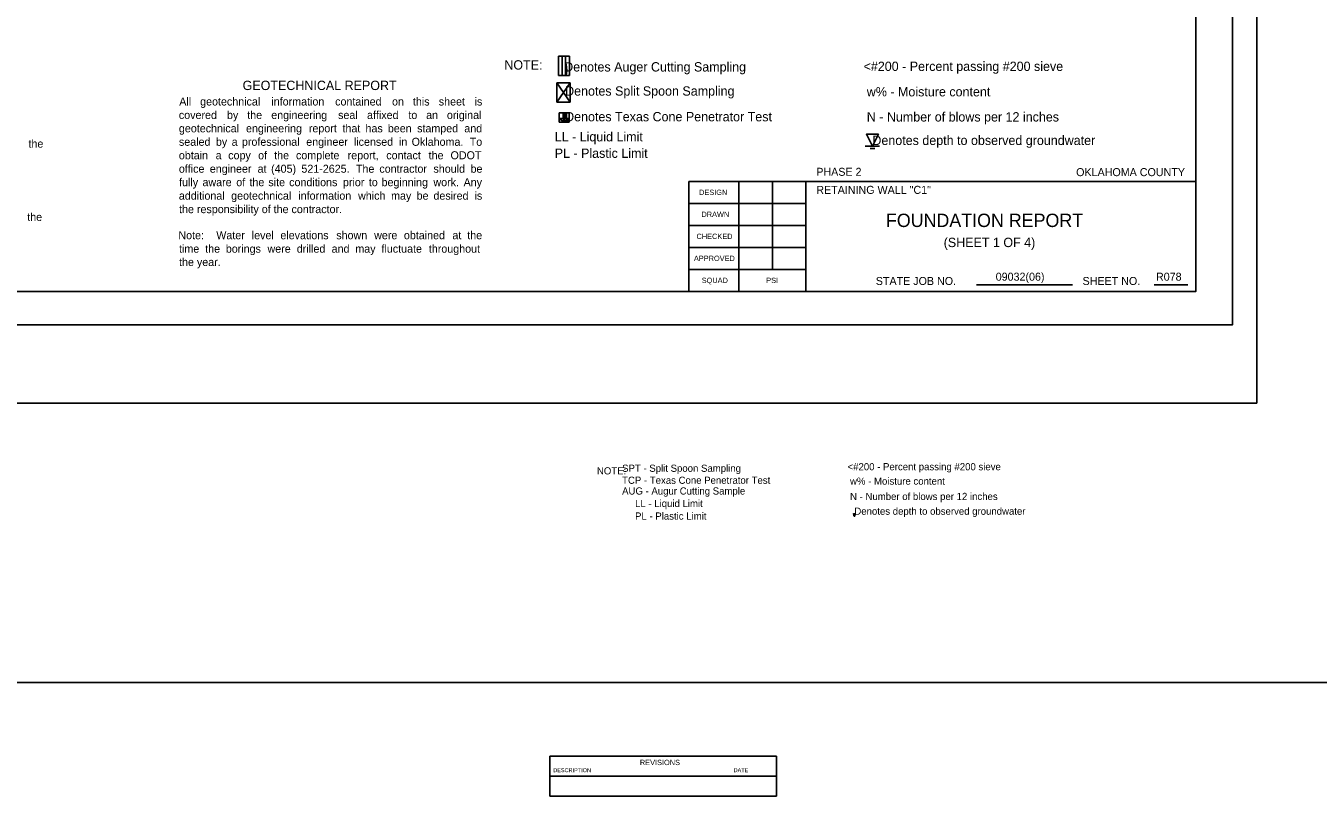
# Model space of a CAD drawing. Extents: x -6 to 173, y 24 to 64.
# Drawn here: x 24.17 to 43.55, y 24.08 to 35.63 of the extents above; entities that cross this region are included whole.
import ezdxf

# ---------------------------------------------------------------- set-up
doc = ezdxf.new("R2010")
doc.units = 0
for name, color, linetype in [('4', 7, 'Continuous'), ('REVBLK', 7, 'Continuous'), ('S', 7, 'Continuous'), ('SHT_Plot_Shape_Full', 7, 'Continuous'), ('SHT_Plot_Shape_Half', 7, 'Continuous'), ('SHT_Sheet_Border', 7, 'Continuous'), ('SHT_Standard_Sheet_Lines', 7, 'Continuous'), ('SHT_Standard_Sheet_Txt', 7, 'Continuous'), ('T', 7, 'Continuous'), ('T-5', 7, 'Continuous'), ('Text', 7, 'Continuous')]:
    doc.layers.add(name, color=color, linetype=linetype)

# ---------------------------------------------------------------- blocks, each defined once
blk = doc.blocks.new('DGRFC_WTLEV1')
for points in [[(-0.013, 0), (0.013, 0)], [(0, 0), (0.011, 0.021), (-0.011, 0.021), (0, 0)], [(-0.004, -0.004), (0.004, -0.004)]]:
    blk.add_lwpolyline(points)
blk = doc.blocks.new('DGRFC_WTLEV1_1')
for points in [[(-0.005, 0), (0.005, 0)], [(0, 0), (0.00417, 0.00833), (-0.00417, 0.00833), (0, 0)], [(-0.00167, -0.00167), (0.00167, -0.00167)]]:
    blk.add_lwpolyline(points)

msp = doc.modelspace()

# ---------------------------------------------------------------- linework, layer by layer
msp.add_line((32.155, 35.172), (32.155, 34.881))
for points in [[(32.155, 35.172), (32.322, 35.172)], [(32.322, 34.881), (32.322, 35.172)], [(32.155, 34.881), (32.322, 34.881)], [(32.155, 34.881), (32.322, 34.881)]]:
    msp.add_lwpolyline(points)
for points in [[(32.213, 35.172), (32.213, 34.881), (32.263, 34.881), (32.263, 35.172)], [(32.278, 35.005), (32.272, 35.047), (32.263, 35.087), (32.278, 35.005)], [(32.263, 35.087), (32.263, 34.881), (32.278, 35.005), (32.263, 35.087)], [(32.263, 34.881), (32.278, 34.922), (32.278, 35.005), (32.263, 34.881)], [(32.263, 34.881), (32.272, 34.881), (32.278, 34.922), (32.263, 34.881)], [(32.278, 34.922), (32.28, 34.963), (32.278, 35.005), (32.278, 34.922)]]:
    msp.add_lwpolyline(points, close=True)
at = {"layer": 'REVBLK'}
for p, q in [((32.025, 24.676), (35.425, 24.676)), ((32.025, 24.676), (32.025, 24.076)), ((35.425, 24.676), (35.425, 24.076)), ((32.025, 24.376), (35.425, 24.376)), ((32.025, 24.076), (35.425, 24.076))]:
    msp.add_line(p, q, dxfattribs=at)
at = {"layer": 'S'}
msp.add_lwpolyline([(-6.024, 64.421), (172.576, 64.421), (172.576, 25.783), (-6.024, 25.783)], close=True, dxfattribs=at)
at = {"layer": 'SHT_Plot_Shape_Full'}
msp.add_lwpolyline([(6.624, 53.971), (42.624, 53.971), (42.624, 29.971), (6.624, 29.971)], close=True, dxfattribs=at)
at = {"layer": 'SHT_Plot_Shape_Half'}
msp.add_lwpolyline([(8.262, 53.146), (42.262, 53.146), (42.262, 31.146), (8.262, 31.146)], close=True, dxfattribs=at)
at = {"layer": 'SHT_Sheet_Border'}
for p, q in [((34.112, 31.646), (34.112, 33.296)), ((34.112, 33.296), (41.712, 33.296)), ((35.862, 31.646), (35.862, 33.297))]:
    msp.add_line(p, q, dxfattribs=at)
msp.add_lwpolyline([(10.212, 52.646), (41.712, 52.646), (41.712, 31.646), (10.212, 31.646)], close=True, dxfattribs=at)
at = {"layer": 'SHT_Standard_Sheet_Lines'}
for p, q in [((34.862, 31.646), (34.862, 33.297)), ((35.362, 31.976), (35.362, 33.297)), ((38.422, 31.742), (39.863, 31.742)), ((41.087, 31.742), (41.59, 31.742))]:
    msp.add_line(p, q, dxfattribs=at)
for points in [[(35.862, 32.966), (34.112, 32.966)], [(35.862, 32.636), (34.112, 32.636)], [(35.862, 32.306), (34.112, 32.306)], [(35.862, 31.976), (34.112, 31.976)]]:
    msp.add_lwpolyline(points, dxfattribs=at)
at = {"layer": 'Text'}
for p, q in [((32.131, 34.481), (32.131, 34.773)), ((32.167, 34.181), (32.167, 34.322))]:
    msp.add_line(p, q, dxfattribs=at)
for points in [[(32.131, 34.481), (32.331, 34.773)], [(32.131, 34.773), (32.331, 34.481)], [(32.131, 34.773), (32.331, 34.773)], [(32.331, 34.481), (32.331, 34.773)], [(32.131, 34.481), (32.331, 34.481)], [(32.167, 34.322), (32.317, 34.322)], [(32.317, 34.181), (32.317, 34.322)], [(32.167, 34.181), (32.317, 34.181)]]:
    msp.add_lwpolyline(points, dxfattribs=at)
for points in [[(32.227, 34.237), (32.257, 34.322), (32.227, 34.322), (32.227, 34.237)], [(32.227, 34.237), (32.257, 34.237), (32.257, 34.322), (32.227, 34.237)], [(32.227, 34.237), (32.167, 34.237), (32.242, 34.181), (32.227, 34.237)], [(32.227, 34.237), (32.242, 34.181), (32.257, 34.237), (32.227, 34.237)], [(32.242, 34.181), (32.317, 34.237), (32.257, 34.237), (32.242, 34.181)]]:
    msp.add_lwpolyline(points, close=True, dxfattribs=at)

# ---------------------------------------------------------------- block references
at = {"xscale": 1.3824000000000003, "yscale": 1.3824000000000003}
msp.add_blockref('DGRFC_WTLEV1', (36.592, 28.283), dxfattribs=at)
at = {"layer": 'Text', "xscale": 21.6, "yscale": 21.6}
msp.add_blockref('DGRFC_WTLEV1_1', (36.863, 33.823), dxfattribs=at)

# ---------------------------------------------------------------- texts
at = {"layer": '4'}
msp.add_text('FOUNDATION REPORT', height=0.2, dxfattribs=at).set_placement((37.065, 32.611))
at = {"layer": 'REVBLK'}
for s, height, p in [('REVISIONS', 0.08, (33.376, 24.542)), ('DESCRIPTION', 0.06, (32.077, 24.436)), ('DATE', 0.06, (34.781, 24.436))]:
    msp.add_text(s, height=height, dxfattribs=at).set_placement(p)
at = {"layer": 'SHT_Standard_Sheet_Txt'}
for s, height, p in [('DESIGN', 0.08, (34.264, 33.091)), ('DRAWN', 0.08, (34.299, 32.761)), ('CHECKED', 0.08, (34.225, 32.431)), ('APPROVED', 0.08, (34.186, 32.101)), ('SQUAD', 0.08, (34.303, 31.771)), ('PSI', 0.08, (35.27, 31.771)), ('STATE JOB NO.', 0.12, (36.913, 31.742)), ('SHEET NO. ', 0.12, (40.013, 31.742))]:
    msp.add_text(s, height=height, dxfattribs=at).set_placement(p)
at = {"layer": 'T'}
for s, p in [('PHASE 2', (36.021, 33.379)), ('OKLAHOMA COUNTY', (39.917, 33.374)), ('RETAINING WALL "C1" ', (36.021, 33.108)), ('09032(06)', (38.711, 31.806)), ('R078', (41.114, 31.806))]:
    msp.add_text(s, height=0.12, dxfattribs=at).set_placement(p)
at = {"layer": 'T-5'}
msp.add_text('(SHEET 1 OF 4)', height=0.14, dxfattribs=at).set_placement((37.931, 32.31))
at = {"layer": 'Text'}
for s, height, p in [('NOTE:', 0.14, (31.344, 34.972)), ('    Denotes Auger Cutting Sampling', 0.14, (32.033, 34.943)), (' <#200 - Percent passing #200 sieve', 0.14, (36.678, 34.951)), ('GEOTECHNICAL REPORT', 0.14, (27.42, 34.665)), ('    Denotes Split Spoon Sampling', 0.14, (32.047, 34.581)), ('w% - Moisture content', 0.14, (36.778, 34.57)), ('All', 0.12, (26.47, 34.433)), ('geotechnical', 0.12, (26.783, 34.433)), ('information', 0.12, (27.851, 34.433)), ('contained', 0.12, (28.807, 34.433)), ('on', 0.12, (29.66, 34.433)), ('this', 0.12, (29.973, 34.433)), ('sheet', 0.12, (30.361, 34.433)), ('is ', 0.12, (30.897, 34.433)), ('covered', 0.12, (26.464, 34.231)), ('by', 0.12, (27.186, 34.231)), ('the', 0.12, (27.489, 34.231)), ('engineering', 0.12, (27.849, 34.231)), ('seal', 0.12, (28.851, 34.231)), ('affixed', 0.12, (29.285, 34.231)), ('to', 0.12, (29.905, 34.231)), ('an', 0.12, (30.171, 34.231)), ('original ', 0.12, (30.483, 34.231)), ('    Denotes Texas Cone Penetrator Test', 0.14, (32.047, 34.196)), ('N - Number of blows per 12 inches', 0.14, (36.778, 34.193)), ('geotechnical', 0.12, (26.465, 34.031)), ('engineering', 0.12, (27.471, 34.031)), ('report', 0.12, (28.413, 34.031)), ('that', 0.12, (28.917, 34.031)), ('has', 0.12, (29.262, 34.031)), ('been', 0.12, (29.597, 34.031)), ('stamped', 0.12, (30.036, 34.031)), ('and ', 0.12, (30.744, 34.031)), ('the ', 0.12, (24.209, 33.801)), ('sealed', 0.12, (26.465, 33.829)), ('by', 0.12, (27.019, 33.829)), ('a', 0.12, (27.256, 33.829)), ('professional', 0.12, (27.409, 33.829)), ('engineer', 0.12, (28.374, 33.829)), ('licensed', 0.12, (29.088, 33.829)), ('in', 0.12, (29.764, 33.829)), ('Oklahoma.', 0.12, (29.954, 33.829)), ('To ', 0.12, (30.825, 33.829)), (' LL - Liquid Limit', 0.14, (32.047, 33.895)), ('    Denotes depth to observed groundwater', 0.14, (36.654, 33.841)), ('obtain', 0.12, (26.464, 33.627)), ('a', 0.12, (27.016, 33.627)), ('copy', 0.12, (27.204, 33.627)), ('of', 0.12, (27.652, 33.627)), ('the', 0.12, (27.893, 33.627)), ('complete', 0.12, (28.22, 33.627)), ('report,', 0.12, (28.995, 33.627)), ('contact', 0.12, (29.574, 33.627)), ('the', 0.12, (30.209, 33.627)), ('ODOT ', 0.12, (30.537, 33.627)), (' PL - Plastic Limit', 0.14, (32.047, 33.648)), ('office', 0.12, (26.464, 33.425)), ('engineer', 0.12, (26.928, 33.425)), ('at', 0.12, (27.645, 33.425)), ('(405)', 0.12, (27.847, 33.425)), ('521-2625.', 0.12, (28.301, 33.425)), ('The', 0.12, (29.119, 33.425)), ('contractor', 0.12, (29.47, 33.425)), ('should', 0.12, (30.281, 33.425)), ('be ', 0.12, (30.837, 33.425)), ('fully', 0.12, (26.468, 33.223)), ('of', 0.12, (27.325, 33.223)), ('the', 0.12, (27.522, 33.223)), ('site', 0.12, (27.806, 33.223)), ('conditions', 0.12, (28.118, 33.223)), ('prior', 0.12, (28.924, 33.223)), ('to', 0.12, (29.312, 33.223)), ('beginning', 0.12, (29.503, 33.223)), ('work.', 0.12, (30.281, 33.223)), ('Any ', 0.12, (30.733, 33.223)), ('additional', 0.12, (26.464, 33.021)), ('aware', 0.12, (26.818, 33.223)), ('geotechnical', 0.12, (27.248, 33.021)), ('information', 0.12, (28.255, 33.021)), ('which', 0.12, (29.151, 33.021)), ('be', 0.12, (30.029, 33.021)), ('desired', 0.12, (30.281, 33.021)), ('is ', 0.12, (30.897, 33.021)), ('the responsibility of the contractor.', 0.12, (26.467, 32.819)), ('may', 0.12, (29.646, 33.021)), ('the ', 0.12, (24.191, 32.701)), ('level', 0.12, (27.557, 32.428)), ('elevations', 0.12, (27.986, 32.428)), ('shown', 0.12, (28.824, 32.428)), ('obtained', 0.12, (29.838, 32.428)), ('the ', 0.12, (30.788, 32.428)), ('Note:', 0.12, (26.457, 32.428)), ('Water', 0.12, (27.025, 32.428)), ('were', 0.12, (29.392, 32.428)), ('at', 0.12, (30.565, 32.428)), ('time', 0.12, (26.467, 32.226)), ('the', 0.12, (26.859, 32.226)), ('borings', 0.12, (27.168, 32.226)), ('were', 0.12, (27.793, 32.226)), ('drilled', 0.12, (28.232, 32.226)), ('and', 0.12, (28.755, 32.226)), ('may', 0.12, (29.11, 32.226)), ('fluctuate', 0.12, (29.502, 32.226)), ('throughout ', 0.12, (30.212, 32.226)), ('the year.', 0.12, (26.467, 32.026)), (' <#200 - Percent passing #200 sieve', 0.10752, (36.45, 28.963)), ('NOTE:', 0.1075, (32.732, 28.901)), ('    SPT - Split Spoon Sampling', 0.10752, (32.95, 28.94)), ('    AUG - Augur Cutting Sample', 0.10752, (32.95, 28.599)), ('    TCP - Texas Cone Penetrator Test', 0.10752, (32.95, 28.76)), ('w% - Moisture content', 0.10752, (36.527, 28.747)), (' LL - Liquid Limit', 0.10752, (33.264, 28.412)), ('N - Number of blows per 12 inches', 0.10752, (36.527, 28.517)), (' PL - Plastic Limit', 0.10752, (33.264, 28.223)), ('    Denotes depth to observed groundwater', 0.10752, (36.432, 28.296))]:
    msp.add_text(s, height=height, dxfattribs=at).set_placement(p)

doc.saveas('drawing.dxf')
